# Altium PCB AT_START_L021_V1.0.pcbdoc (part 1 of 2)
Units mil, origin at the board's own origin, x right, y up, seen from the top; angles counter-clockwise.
Board outline 12992.58 x 3605 mil, 2 copper layers (Top Layer, Bottom Layer); 116 components, 109 nets, 471 pads, 502 vias.
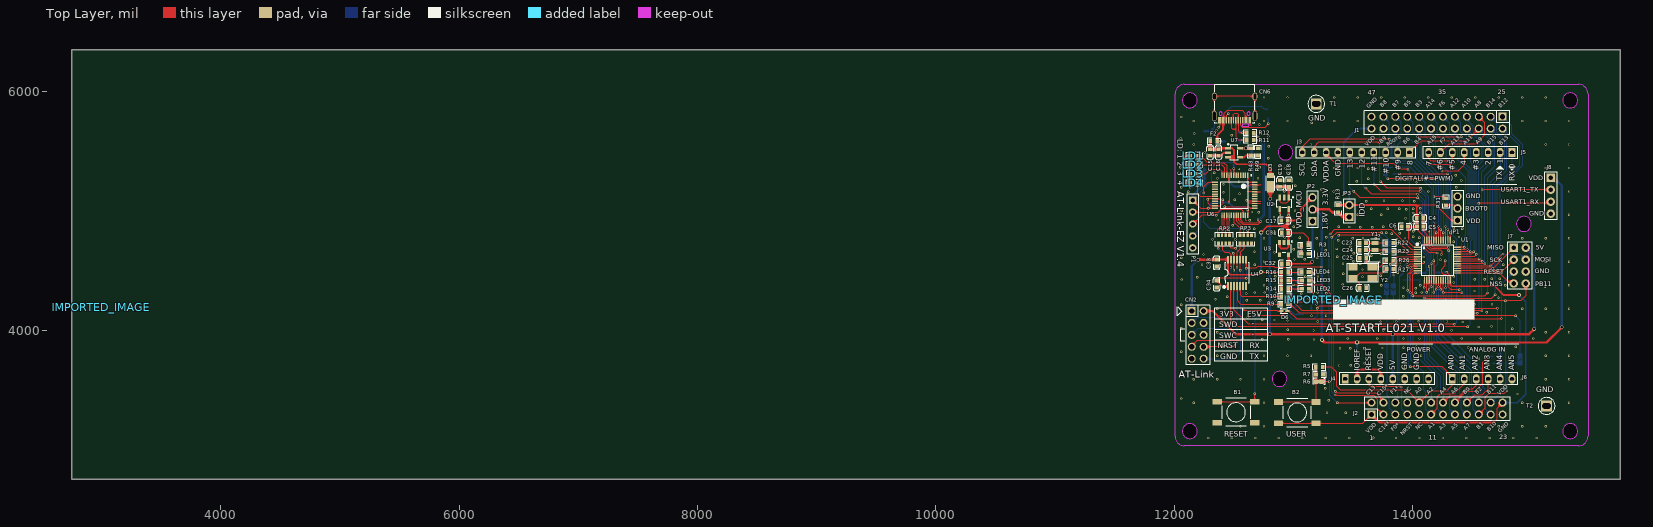
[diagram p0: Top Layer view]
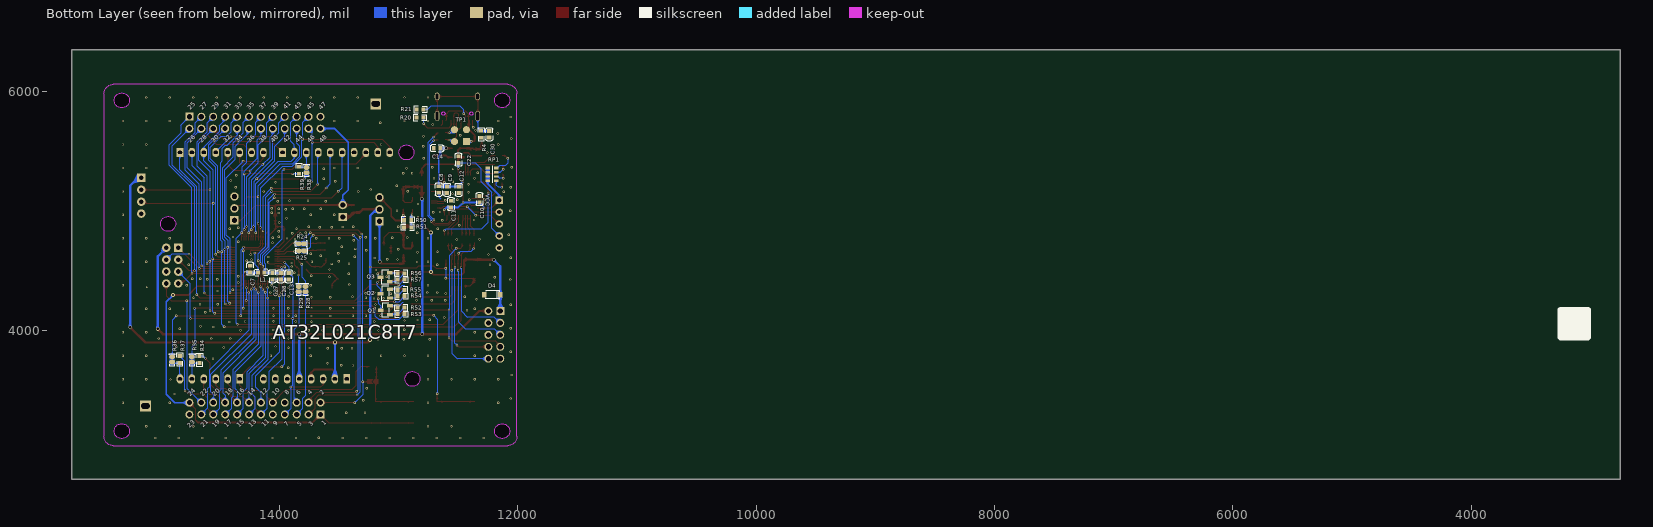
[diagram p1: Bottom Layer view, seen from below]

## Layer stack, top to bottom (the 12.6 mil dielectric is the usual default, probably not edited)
Top Layer: signal copper (thickness not stored)
Dielectric: dielectric 12.6, FR-4, Dk 4.8
Bottom Layer: signal copper (thickness not stored)

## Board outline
15742.58,2750 2750,2750 2750,6355 15742.58,6355
cut-out: 15384.57,5929.2 ccw(c15321.57,5929.2) 15258.58,5929.2 ccw(c15321.57,5929.2)
cut-out: 15384.57,3154.52 ccw(c15321.57,3154.52) 15258.58,3154.52 ccw(c15321.57,3154.52)
cut-out: 12193.58,3154.52 ccw(c12130.59,3154.23) 12067.6,3154.52 ccw(c12130.59,3154.81)
cut-out: 12193.58,5929.2 ccw(c12130.59,5928.92) 12067.6,5929.2 ccw(c12130.59,5929.49)
cut-out: 14996.34,4892.35 ccw(c14933.34,4892.35) 14870.35,4892.35 ccw(c14933.34,4892.35)
cut-out: 12946.34,3592.35 ccw(c12883.34,3592.35) 12820.35,3592.35 ccw(c12883.34,3592.35)
cut-out: 12996.34,5492.35 ccw(c12933.34,5492.35) 12870.35,5492.35 ccw(c12933.34,5492.35)

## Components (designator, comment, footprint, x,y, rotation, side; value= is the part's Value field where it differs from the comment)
B1 "K2-1102SP-C4SC-04" BUTTON_SMT_6*6*5 12517.98,3312.6 r0 top
B2 "K2-1102SP-C4SC-04" BUTTON_SMT_6*6*5 13031.98,3310.61 r180 top
C4 "CL10A475KO8NNNC" C0603 14061.58,4941 r180 top
C5 "CC0603KRX7R9BB104" C0603 14063.58,4871 r180 top
C6 "CC0603KRX7R9BB104" C0603 13933.58,4870 r0 top
C7 "CC0603KRX7R9BB104" C0603 14244.58,4515 r270 bottom
C8 "CL10A475KO8NNNC" C0603 12662.58,5182 r90 bottom
C9 "CC0603KRX7R9BB104" C0603 12592.58,5180 r90 bottom
C10 "CC0603KRX7R9BB104" C0603 12320.58,5100 r270 bottom
C11 "CC0603KRX7R9BB104" C0603 12559.58,5059 r270 bottom
C12 "CC0603KRX7R9BB104" C0603 12495.58,5180 r90 bottom
C13 "CC0603KRX7R9BB104" C0603 13920.58,4453 r90 bottom
C14 "CL10A106KP8NNNC" C0603 12676.58,5527 r180 bottom
C15 "CL10A106KP8NNNC" C0603 12301.58,5492 r90 top
C16 "CC0603KRX7R9BB104" C0603 12371.58,5492 r90 top
C17 "CL10A106KP8NNNC" C0603 12924.58,4921 r0 top
C18 "CL10A106KP8NNNC" C0603 12960.58,5231 r270 top
C19 "CC0603KRX7R9BB104" C0603 12889.58,5232 r270 top
C22 "CC0603KRX7R9BB104" C0603 12496.58,5432 r270 bottom
C23 "CL10C180JB8NNNC" C0603 13581.98,4732.6 r0 top
C24 "CL10C180JB8NNNC" C0603 13581.98,4673.6 r0 top
C25 "CL10C330JB8NNNC" C0603 13582.58,4605 r0 top
C26 "CL10C330JB8NNNC" C0603 13582.58,4355 r180 top
C27 "CL10A105KB8NNNC" C0603 14057.58,4454 r90 bottom
C28 "CC0603KRX7R9BB104" C0603 13988.58,4453 r90 bottom
C30 "CC0603KRX7R9BB104" C0603 12238.9,5644.56 r90 bottom
C31 "CL10A105KB8NNNC" C0603 12928.58,4819 r0 top
C32 "CL10A105KB8NNNC" C0603 12926.58,4558 r0 top
C33 "CC0603KRX7R9BB104" C0603 12355.58,4566 r270 top
C34 "CC0603KRX7R9BB104" C0603 12355.58,4388 r90 top
CN2 "Z-21310110021001" HDR-TH_10P-P2.54-V-M-R2-C5-S2.54 12196.58,3962 r270 top
CN6 "TYPEC-304-BCP16" USB-C-SMD_TYPEC-304-BCP16 12506.58,5862 r180 top
D3 "DFLS130L-7_POWERDI-123_L2.8-W1.8-LS3.7-RD" POWERDI-123_L2.8-W1.8-LS3.7-RD 12805.58,5251 r90 top
D4 "SMF3.3A" SOD-123_L2.8-W1.8-LS3.7-RD 12213.58,4299 r0 bottom
D6 "LRB521S-40T1G" SOD-523_L1.2-W0.8-LS1.6-RD 12924.58,4162 r0 top
F2 "SMD0603B050TF" R0603 12331.58,5587 r180 top
IMPORTED_IMAGE "IMPORTED_IMAGE" IMPORTED_IMAGE 3000,4194 r0 top
IMPORTED_IMAGE "IMPORTED_IMAGE" IMPORTED_IMAGE 13334.58,4257 r0 top
J1 "PZ254V-12-24P" HDR-TH_24P-P2.54-V-M-R2-C12-S2.54 14204.6,5742.09 r180 top
J2 "PZ254V-12-24P" HDR-TH_24P-P2.54-V-M-R2-C12-S2.54 14204.61,3343.91 r0 top
J3 "2.54-1*10P母" "AT-START-Connector 1x10" 13523.35,5492.35 r180 top
J4 "2.54-1*8P母环保" "AT-START-Connector 1x8" 13783.35,3592.35 r0 top
J5 "2.54-1*8P母环保" "AT-START-Connector 1x8" 14483.35,5492.35 r180 top
J6 "2.54-1*6P母" "AT-START-Connector 1x6" 14583.33,3592.35 r0 top
J7 "Header 4X2" HDR2X4 14848.35,4692.9 r270 top
J8 "Header 1x4" HDR1X4 15158.58,5279 r270 top
JP1 "Header 1x3" "HEADER 1X3" 14376.58,4923 r90 top
JP2 "Header 1x3" "HEADER 1X3" 13159.58,4915 r90 top
JP3 "NC(Header 1x2)" HDR1X2 13467.58,4951 r90 top
L1 "600Ω@100MHz ±25%" L0603 14151.58,4485 r180 bottom
LD1 "RED" LED0603 12129.79,5464.85 r0 top
LD2 "GREEN" LED0603 12130.75,5390.75 r0 top
LD3 "BLUE" LED0603 12130.79,5313.85 r0 top
LD4 "YELLOW" LED0603 12130.75,5237.85 r0 top
LED1 "RED_LED0603(1)" LED0603 13066.58,4642 r0 top
LED2 "RED_LED0603" LED0603 13069.58,4349 r0 top
LED3 "YELLOW_LED0603" LED0603 13068.58,4418 r0 top
LED4 "GREEN_LED0603" LED0603 13067.58,4490 r0 top
P1 "HDR-M-2.54_1x5" HDR-M-2.54_1X5 12154.58,4892 r270 top
Q1 "SS8050_C916392" SOT-23-3_L2.9-W1.3-P1.90-LS2.4-BR 13109.58,4169 r180 bottom
Q2 "SS8050_C916392" SOT-23-3_L2.9-W1.3-P1.90-LS2.4-BR 13110.58,4308 r180 bottom
Q3 "SS8050_C916392" SOT-23-3_L2.9-W1.3-P1.90-LS2.4-BR 13112.58,4446 r180 bottom
R3 "0603WAF1001T5E" R0603 13095.58,4715 r0 top
R4 "RC0603FR-071ML" R0603 12306.58,5645 r270 bottom
R5 "0603WAF0000T5E" R0603 13216.58,3693 r0 top
R6 "NC_SB-PAD" SB-PAD#1 13215.58,3570 r0 top
R7 "0603WAF1003T5E" R0603 13217.58,3628 r180 top
R9 "0603WAF3300T5E" R0603 12925.58,4220 r0 top
R10 "0603WAF3300T5E" R0603 12926.58,4285 r0 top
R11 "0603WAF0000T5E" R0603 12636.58,5597 r0 top
R12 "0603WAF0000T5E" R0603 12636.58,5657 r0 top
R13 "0603WAF0000T5E" R0603 13373.58,5021 r90 top
R14 "0603WAF1001T5E" R0603 12926.58,4349 r180 top
R15 "0603WAF1001T5E" R0603 12927.58,4418 r180 top
R16 "0603WAF1001T5E" R0603 12926.58,4489 r180 top
R20 "0603WAF5101T5E" R0603 12820.58,5784 r0 bottom
R21 "0603WAF5101T5E" R0603 12819.58,5853 r0 bottom
R22 "0603WAF0000T5E" R0603 13807.58,4732 r0 top
R23 "0603WAF0000T5E" R0603 13808.58,4660 r0 top
R24 "NC" SB-PAD#1 13814.58,4727 r180 bottom
R25 "NC" SB-PAD#1 13813.58,4666 r180 bottom
R26 "0603WAF0000T5E" R0603 13807.58,4585 r0 top
R27 "0603WAF0000T5E" R0603 13809.58,4515 r0 top
R28 "NC" SB-PAD#2 13780.58,4345 r270 bottom
R29 "NC" SB-PAD#2 13837.58,4345 r270 bottom
R31 "0603WAF1002T5E" R0603 14279.58,5079 r90 top
R34 "0603WAF0000T5E" R0603 14670.58,3755 r270 bottom
R35 "NC_SB-PAD" SB-PAD#2 14733.58,3755 r270 bottom
R36 "NC_SB-PAD" SB-PAD#2 14899.58,3755 r270 bottom
R37 "0603WAF0000T5E" R0603 14835.58,3756 r270 bottom
R38 "NC_SB-PAD" SB-PAD#2 13772.58,5343 r270 bottom
R39 "0603WAF0000T5E" R0603 13834.58,5343 r90 bottom
R43 "0603WAF4702T5E" R0603 12641.58,5497 r90 top
R49 "0603WAF1502T5E" R0603 12701.58,5497 r270 top
R50 "0603WAF4702T5E" R0603 12923.58,4927 r0 bottom
R51 "0603WAF1502T5E" R0603 12923.58,4864 r180 bottom
R52 "0603WAF1003T5E" R0603 12978.58,4190 r180 bottom
R53 "0603WAF1002T5E" R0603 12979.13,4136 r0 bottom
R54 "0603WAF1002T5E" R0603 12978.58,4286 r0 bottom
R55 "0603WAF1003T5E" R0603 12978.58,4339 r180 bottom
R56 "0603WAF1003T5E" R0603 12978.58,4478 r180 bottom
R57 "0603WAF1002T5E" R0603 12978.58,4425 r0 bottom
RP1 "1K" 0603*4,8P4R 12251.58,5362 r270 bottom
RP2 "4D03WGJ0331T5E" RES-ARRAY-SMD_0603-8P-L3.2-W1.6-BL 12416.58,4763 r0 top
RP3 "4D03WGJ0331T5E" RES-ARRAY-SMD_0603-8P-L3.2-W1.6-BL 12599.58,4763 r0 top
T1 "Testpoint_TESTHOOK" TESTHOOK 13191.58,5900 r0 top
T2 "Testpoint" TESTHOOK 15123.58,3366 r180 top
TP1 "1X4P_2.54F" "HDR1X4 - TOP" 12530.58,5483 r270 bottom
U1 "AT32L021C8T7" LQFP-48_L7.0-W7.0-P0.50-LS9.0-BL 14206.98,4588.6 r270 top
U2 "RT9080N-08GJ5" SOT-23-5 12860.58,5051 r270 top
U3 "ME6211C18M5G-N" SOT-23-5_L3.0-W1.7-P0.95-LS2.8-BR 12921.58,4685 r90 top
U4 "RS0104YQ" TSSOP-14_L5.0-W4.4-P0.65-LS6.4-BL 12526.58,4482 r0 top
U6 "AT32F403ACCT7" "LQFP48 - 2" 12616.98,5300.6 r270 top
U7 "RT9080N-08GJ5" SOT-23-5(1) 12516.58,5427 r0 top
Y1 "32.768KHz" "XTAL_SOP - FC-12M" 13685.98,4732.6 r270 top
Y2 "8MHz" OSC-SMD_4P-L5.0-W3.2-BL 13580.58,4482 r180 top

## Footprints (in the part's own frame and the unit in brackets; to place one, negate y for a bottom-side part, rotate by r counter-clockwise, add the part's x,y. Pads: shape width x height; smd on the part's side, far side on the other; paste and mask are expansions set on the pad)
0603*4,8P4R [mm]
  rect 0.55x0.95 smd: 1(0,0) 4(2.7,0) 5(2.7,1.85) 8(0,1.85)
  rect 0.5x0.95 smd: 2(0.9,0) 3(1.8,0) 6(1.8,1.85) 7(0.9,1.85)
  silkscreen extent -0.43,0.94 3.1,0.94
"AT-START-Connector 1x6" [mm]
  rect 1.4x2 hole 0.65 slot 0.9 at 0 deg: 1(-6.35,0)
  oval 1.4x2 hole 0.65 slot 0.9 at 0 deg: 2(-3.81,0) 3(-1.27,0) 4(1.27,0) 5(3.81,0) 6(6.35,0)
  silkscreen extent -7.62,-1.17 7.62,1.27
"AT-START-Connector 1x8" [mm]
  rect 1.4x2 hole 0.65 slot 0.9 at 0 deg: 1(-8.89,0)
  oval 1.4x2 hole 0.65 slot 0.9 at 0 deg: 2(-6.35,0) 3(-3.81,0) 4(-1.27,0) 5(1.27,0) 6(3.81,0) 7(6.35,0) 8(8.89,0)
  silkscreen extent -10.16,-1.17 10.16,1.27
"AT-START-Connector 1x10" [mm]
  rect 1.4x2 hole 0.65 slot 0.9 at 0 deg: 1(-11.43,0)
  oval 1.4x2 hole 0.65 slot 0.9 at 0 deg: 2(-8.89,0) 3(-6.35,0) 4(-3.81,0) 5(-1.27,0) 6(1.27,0) 7(3.81,0) 8(6.35,0) 9(8.89,0) 10(11.43,0)
  silkscreen extent -12.7,-1.17 12.67,1.27
BUTTON_SMT_6*6*5 [mm]
  rect 2x1.2 smd: 1(-4,2.25) 2(4,2.25) 3(-4,-2.25) 4(4,-2.25)
  silkscreen extent -3,-3 3,3
C0603 [mm]
  rect 0.8x0.9 smd: 1(-0.7,0) 2(0.7,0)
  silkscreen extent -1.41,-0.71 1.39,0.72
HDR1X2 [mm]
  rect 1.8x1.8 hole 1 slot 1.005 at 0 deg: 1(0,0)
  round 1.8 hole 1 slot 1.005 at 0 deg: 2(2.54,0)
  silkscreen extent -1.27,-1.27 3.81,1.27
HDR1X4 [mm]
  rect 1.8x1.8 hole 1: 1(0,0)
  round 1.8 hole 1: 2(2.54,0) 3(5.08,0) 4(7.62,0)
  silkscreen extent -1.27,-1.27 8.89,1.27
"HDR1X4 - TOP" [mm]
  rect 1.5x1.5 smd: 1(-2.54,2.54)
  round 1.5 smd: 2(-5.08,0) 3(-2.54,0) 4(-5.08,2.54)
HDR2X4 [mm]
  rect 1.8x1.8 hole 1: 1(0,0)
  round 1.8 hole 1: 2(0,2.54) 3(2.54,0) 4(2.54,2.54) 5(5.08,0) 6(5.08,2.54) 7(7.62,0) 8(7.62,2.54)
  silkscreen extent -1.27,-1.27 8.89,3.81
HDR-M-2.54_1X5 [mil]
  rect 62x62 hole 35: 1(-200,0)
  round 62 hole 35: 2(-100,0) 3(0,0) 4(100,0) 5(200,0)
  silkscreen extent -250,-50 250,50
HDR-TH_10P-P2.54-V-M-R2-C5-S2.54 [mm]
  rect 1.7x1.7 hole 1.1: 1(-5.08,-1.27)
  round 1.7 hole 1.1: 2(-5.08,1.27) 3(-2.54,-1.27) 4(-2.54,1.27) 5(0,-1.27) 6(0,1.27) 7(2.54,-1.27) 8(2.54,1.27) 9(5.08,-1.27) 10(5.08,1.27)
  silkscreen extent -6.35,-2.54 6.35,2.54
HDR-TH_24P-P2.54-V-M-R2-C12-S2.54 [mil]
  rect 66.9x66.9 hole 43.3: 1(-550,-50)
  round 66.9 hole 43.3: 2(-550,50) 3(-450,-50) 4(-450,50) 5(-350,-50) 6(-350,50) 7(-250,-50) 8(-250,50) 9(-150,-50) 10(-150,50) 11(-50,-50) 12(-50,50) 13(50,-50) 14(50,50) 15(150,-50) 16(150,50) 17(250,-50) 18(250,50) 19(350,-50) 20(350,50) 21(450,-50) 22(450,50) 23(550,-50) 24(550,50)
  silkscreen extent -609,-100 609,100
"HEADER 1X3" [mm]
  rect 1.8x1.8 hole 1 slot 1.005 at 0 deg: 1(0,0)
  round 1.8 hole 1 slot 1.005 at 0 deg: 2(2.54,0) 3(5.08,0)
  silkscreen extent -1.27,-1.27 6.35,1.27
IMPORTED_IMAGE [mil]
L0603 [mil]
  rect 31.5x34 smd: 1(-27.6,0) 2(27.6,0)
  silkscreen extent -56,-26 56,26
LED0603 [mil]
  rect 36x32 smd: 1(-0.04,0.2) 2(60.96,0.2)
  silkscreen extent -28,-28 110,27
"LQFP48 - 2" [mm]
  rect 1.2x0.3 smd: 1(0,0) 2(0,-0.5) 3(0,-1) 4(0,-1.5) 5(0,-2) 6(0,-2.5) 7(0,-3) 8(0,-3.5) 9(0,-4) 10(0,-4.5) 11(0,-5) 12(0,-5.5) 25(8.5,-5.5) 26(8.5,-5) 27(8.5,-4.5) 28(8.5,-4) 29(8.5,-3.5) 30(8.5,-3) 31(8.5,-2.5) 32(8.5,-2) 33(8.5,-1.5) 34(8.5,-1) 35(8.5,-0.5) 36(8.5,0)
  rect 0.3x1.2 smd: 13(1.5,-7) 14(2,-7) 15(2.5,-7) 16(3,-7) 17(3.5,-7) 18(4,-7) 19(4.5,-7) 20(5,-7) 21(5.5,-7) 22(6,-7) 23(6.5,-7) 24(7,-7) 37(7,1.5) 38(6.5,1.5) 39(6,1.5) 40(5.5,1.5) 41(5,1.5) 42(4.5,1.5) 43(4,1.5) 44(3.5,1.5) 45(3,1.5) 46(2.5,1.5) 47(2,1.5) 48(1.5,1.5)
  silkscreen extent -0.12,-5.71 7.11,0.89
LQFP-48_L7.0-W7.0-P0.50-LS9.0-BL [mil]
  oval 10.6x59.1 smd: 1(-108.3,-167.3) 2(-88.6,-167.3) 3(-68.9,-167.3) 4(-49.2,-167.3) 5(-29.5,-167.3) 6(-9.8,-167.3) 7(9.8,-167.3) 8(29.5,-167.3) 9(49.2,-167.3) 10(68.9,-167.3) 11(88.6,-167.3) 12(108.3,-167.3) 25(108.3,167.3) 26(88.6,167.3) 27(68.9,167.3) 28(49.2,167.3) 29(29.5,167.3) 30(9.8,167.3) 31(-9.8,167.3) 32(-29.5,167.3) 33(-49.2,167.3) 34(-68.9,167.3) 35(-88.6,167.3) 36(-108.3,167.3)
  oval 59.1x10.6 smd: 13(167.3,-108.3) 14(167.3,-88.6) 15(167.3,-68.9) 16(167.3,-49.2) 17(167.3,-29.5) 18(167.3,-9.8) 19(167.3,9.8) 20(167.3,29.5) 21(167.3,49.2) 22(167.3,68.9) 23(167.3,88.6) 24(167.3,108.3) 37(-167.3,108.3) 38(-167.3,88.6) 39(-167.3,68.9) 40(-167.3,49.2) 41(-167.3,29.5) 42(-167.3,9.8) 43(-167.3,-9.8) 44(-167.3,-29.5) 45(-167.3,-49.2) 46(-167.3,-68.9) 47(-167.3,-88.6) 48(-167.3,-108.3)
  silkscreen extent -141,-176 130,132
OSC-SMD_4P-L5.0-W3.2-BL [mm]
  rect 2x1.4 smd: 1(-2.05,-1.2) 2(2.05,-1.2) 3(2.05,1.2) 4(-2.05,1.2)
  silkscreen extent -3.46,-2.26 3.24,2.03
POWERDI-123_L2.8-W1.8-LS3.7-RD [mm]
  rect 2.4x1.5 smd: 1(-1.187,0)
  rect 1.05x1.5 smd: 2(1.187,0)
  silkscreen extent -2,-1 1.2,1
R0603 [mil]
  rect 31.75x34.02 smd: 1(-29.66,0) 2(29.66,0)
  silkscreen extent -55,-26 55,26
RES-ARRAY-SMD_0603-8P-L3.2-W1.6-BL [mm]
  rect 0.65x0.8 smd: 1(-1.2,-0.9) 4(1.2,-0.9) 5(1.2,0.9) 8(-1.2,0.9)
  rect 0.5x0.8 smd: 2(-0.4,-0.9) 3(0.4,-0.9) 6(0.4,0.9) 7(-0.4,0.9)
  silkscreen extent -1.87,-1.45 1.87,1.47
SB-PAD#1 [mm]
  oval 1.225x1 smd: 1(-0.587,0)
  oval 1.319x1 smd: 2(0.541,0)
  Top Layer region: -1.2,-0.5 -1.2,0.5 -0.418,0.5 0.025,0 -0.433,-0.5
  Top Layer region: -0.119,0.5 0.381,0 -0.119,-0.5 1.2,-0.5 1.2,0.5
  silkscreen extent -1.28,-0.58 1.28,0.58
SB-PAD#2 [mm]
  oval 1x1.225 smd: 1(-0.587,0)
  oval 1x1.319 smd: 2(0.541,0)
  Top Layer region: -1.2,-0.5 -1.2,0.5 -0.418,0.5 0.025,0 -0.433,-0.5
  Top Layer region: -0.119,0.5 0.381,0 -0.119,-0.5 1.2,-0.5 1.2,0.5
  silkscreen extent -1.28,-0.58 1.28,0.58
SOD-123_L2.8-W1.8-LS3.7-RD [mm]
  rect 0.95x1.15 smd: 1(-1.692,0) 2(1.692,0)
  silkscreen extent -1.63,-0.94 1.41,0.94
SOD-523_L1.2-W0.8-LS1.6-RD [mm]
  rect 0.93x0.36 smd: 1(-0.635,0) 2(0.635,0)
  silkscreen extent -0.91,-0.55 0.68,0.55
SOT-23-3_L2.9-W1.3-P1.90-LS2.4-BR [mm]
  rect 1.25x0.7 smd: 1(1,-0.95) 2(1,0.95) 3(-1,0)
  silkscreen extent -0.73,-1.53 0.73,1.53
SOT-23-5 [mil]
  rect 50x20 smd: 1(-65,100) 2(-65,63) 3(-65,25) 4(35,25) 5(35,100)
  silkscreen extent -65,1 18,135
SOT-23-5(1) [mil]
  rect 50x20 smd: 1(-65,100) 2(-65,63) 3(-65,25) 4(35,25) 5(35,100)
  silkscreen extent -65,1 18,135
SOT-23-5_L3.0-W1.7-P0.95-LS2.8-BR [mm]
  rect 1x0.6 smd: 1(1.3,-0.95) 2(1.3,0) 3(1.3,0.95) 4(-1.3,0.95) 5(-1.3,-0.95)
  silkscreen extent -0.9,-1.78 1.65,1.55
TESTHOOK [mm]
  rect 2.3x2.3 hole 1.2 slot 1.8 at 0 deg: 1(0,0)
  silkscreen extent -1.79,-1.8 1.8,1.8
TSSOP-14_L5.0-W4.4-P0.65-LS6.4-BL [mm]
  rect 0.4x1.7 smd: 1(-1.95,-2.8) 2(-1.3,-2.8) 3(-0.65,-2.8) 4(0,-2.8) 5(0.65,-2.8) 6(1.3,-2.8) 7(1.95,-2.8) 8(1.95,2.8) 9(1.3,2.8) 10(0.65,2.8) 11(0,2.8) 12(-0.65,2.8) 13(-1.3,2.8) 14(-1.95,2.8)
  silkscreen extent -2.95,-3.2 2.5,2.25
USB-C-SMD_TYPEC-304-BCP16 [mil]
  oval 39.4x82.7 hole 23.6 slot 70.9 at 90 deg: 13(-170.1,64.3) 14(170.1,64.3)
  oval 39.4x63 hole 23.6 slot 47.2 at 90 deg: 15(-170.1,-100.3) 16(170.1,-100.3)
  rect 23.6x57.1 smd: A1B12(-127,100.3) A4B9(-96.5,100.3) B1A12(126.8,100.3) B4A9(96.5,100.3)
  rect 11.8x57.1 smd: A5(-49.2,100.3) A6(-9.8,100.3) A7(9.8,100.3) A8(49.2,100.3) B5(68.9,100.3) B6(29.5,100.3) B7(-29.5,100.3) B8(-68.9,100.3)
  Multi-Layer board cut-out: 103.5,43.4 104.87,37.41 108.7,32.61 114.23,29.94 120.37,29.94 125.91,32.61 129.74,37.41 131.11,43.4 131.11,43.4 129.74,49.39 125.91,54.19 120.37,56.86 114.23,56.86 108.7,54.19 104.87,49.39 103.5,43.4
  Multi-Layer board cut-out: -131.1,43.4 -129.73,37.41 -125.9,32.61 -120.37,29.94 -114.23,29.94 -108.69,32.61 -104.86,37.41 -103.49,43.4 -103.49,43.4 -104.86,49.39 -108.69,54.19 -114.23,56.86 -120.37,56.86 -125.9,54.19 -129.73,49.39 -131.1,43.4
  Multi-Layer keep-out region: 103.5,43.4 104.87,37.41 108.7,32.61 114.23,29.94 120.37,29.94 125.91,32.61 129.74,37.41 131.11,43.4 131.11,43.4 129.74,49.39 125.91,54.19 120.37,56.86 114.23,56.86 108.7,54.19 104.87,49.39 103.5,43.4
  Multi-Layer keep-out region: -131.1,43.4 -129.73,37.41 -125.9,32.61 -120.37,29.94 -114.23,29.94 -108.69,32.61 -104.86,37.41 -103.49,43.4 -103.49,43.4 -104.86,49.39 -108.69,54.19 -114.23,56.86 -120.37,56.86 -125.9,54.19 -129.73,49.39 -131.1,43.4
  silkscreen extent -170,-200 170,120
"XTAL_SOP - FC-12M" [mm]
  rect 0.8x1.5 smd: 1(0,0) 2(1.5,0)
  silkscreen extent -0.81,-0.99 2.29,0.94

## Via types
v1: diameter 19.68, hole 11.81, Top Layer to Bottom Layer, 217 vias
v2: diameter 19.7, hole 11.8, Top Layer to Bottom Layer, 181 vias
v3: diameter 19.7, hole 11.81, Top Layer to Bottom Layer, 91 vias
v4: diameter 31.5, hole 19.68, Top Layer to Bottom Layer, 13 vias

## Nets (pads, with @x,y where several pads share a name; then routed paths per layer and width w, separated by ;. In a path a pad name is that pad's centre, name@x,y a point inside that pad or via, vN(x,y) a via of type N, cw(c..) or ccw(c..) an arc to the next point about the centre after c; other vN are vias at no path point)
1V8: C32.2 JP2.1 U3.5 | length 629.7
  Top Layer w15: U3.5@12958.98,4633.81 12958.98,4562.84 C32.2@12954.14,4558 13141.58,4558 v4(13158.58,4575)
  Bottom Layer w15: v4(13158.58,4575) 13159.58,4576.01 JP2.1@13159.59,4915
3V3: C17.2 C31.2 C33.1 CN2.1 D4.1 JP2.3 R3.2 R14.2 R15.2 R16.2 R50.2 U2.5 U3.1 U3.3 U4.14 | length 3048.3
  Top Layer w10: v4(12727.58,4489) R16.2@12896.92,4489 R14.2@12896.92,4349 ; C31.2@12956.14,4819 13083.58,4819 13125.24,4777.34 R3.2@13125.24,4715
  Top Layer w15: C33.1@12355.58,4593.56 12448.49,4593.56 U4.14@12449.81,4592.24 12449.81,4487.77 12470.58,4467 12706.58,4467 12727.58,4488 v4(12727.58,4489) ; v4(12728.58,4821) 12780.44,4872.87 12952.14,4872.87 ; U3.3@12884.17,4736.19 12884.17,4700.4 12898.58,4686 12944.58,4686 12958.98,4700.4 U3.1@12958.98,4736.19 12958.98,4816.16 C31.2@12956.14,4819 12952.14,4823 12952.14,4872.87 ; U2.5@12960.58,5016 v3(12960.58,4966.73) 12952.14,4958.29 C17.2@12952.14,4921 ; JP2.3@13159.59,5115 13061.58,5016.99 13061.58,4958 13024.58,4921 C17.2@12952.14,4921 ; 12952.14,4872.87 C17.2@12952.14,4921
  Top Layer w20: v4(12201.58,4592) 12203.14,4593.56 C33.1@12355.58,4593.56
  Bottom Layer w6: R50.2@12953.24,4927 12960.58,4934.34 v3(12960.58,4966.73)
  Bottom Layer w15: v4(12727.58,4489) 12727.58,4820 v4(12728.58,4821)
  Bottom Layer w20: CN2.1@12146.58,4162 D4.1@12146.58,4298.63 ; D4.1@12146.94,4299 D4.1@12146.58,4298.63 ; v4(12201.58,4592) 12146.58,4537 D4.1@12146.58,4298.63
$1N349: LD4.1 RP1.5 | length 131.5
  Top Layer w6: LD4.1@12130.7,5238.05 12130.7,5200.87 v1(12132.58,5199)
  Bottom Layer w6: v1(12132.58,5199) 12159.58,5199 12178.75,5218.17 RP1.5@12178.75,5255.7
$1N350: LD3.1 RP1.6 | length 103.9
  Top Layer w6: v1(12121.58,5277) 12121.58,5304.88 LD3.1@12130.75,5314.05
  Bottom Layer w6: v1(12121.58,5277) 12152.54,5277 12166.67,5291.13 RP1.6@12178.75,5291.13
$1N351: LD2.1 RP1.7 | length 110.4
  Top Layer w6: v1(12121.58,5352) 12121.58,5381.82 LD2.1@12130.7,5390.95
  Bottom Layer w6: v1(12121.58,5352) 12147,5326.57 RP1.7@12178.75,5326.57
$1N352: LD1.1 RP1.8 | length 211.2
  Top Layer w6: v1(12082.58,5444) 12103.62,5465.05 LD1.1@12129.75,5465.05
  Bottom Layer w6: v1(12082.58,5444) 12082.58,5401 12100.58,5383 12150.58,5383 12171.58,5362 RP1.8@12178.75,5362
$1N495: R43.1 R49.2 U7.4 | length 156.4
  Top Layer w15: U7.4@12551.58,5452 12586.57,5452 12601.92,5467.34 R43.1@12641.58,5467.34 R49.2@12701.58,5467.34
$1N28282: C15.2 C16.2 D3.2 F2.2 U7.1 U7.3 | length 810.1
  Top Layer w15: C15.2@12301.58,5519.56 C15.2@12301.92,5519.9 ; F2.2@12301.92,5587 C15.2@12301.92,5519.9 ; C16.2@12371.58,5519.56 C16.2@12371.24,5519.9 ; U7.3@12451.58,5452 12500.58,5452 ; D3.2@12805.58,5297.75 12805.58,5358 12770.58,5393 12523.58,5393 12500.58,5416 12500.58,5452 ; C15.2@12301.92,5519.9 C16.2@12371.24,5519.9 ; C16.2@12371.24,5519.9 12378.33,5527 U7.1@12451.58,5527 12485.58,5527 12500.58,5512 12500.58,5452
$2N102: C25.2 R26.1 Y2.1 | length 243.7
  Top Layer w6: C25.2@13610.14,4605 13610.14,4568.44 13649.33,4529.24 Y2.1@13661.28,4529.24 13666.05,4534 13726.92,4534 R26.1@13777.92,4585
$2N103: C26.2 R27.1 Y2.3 | length 412
  Top Layer w6: Y2.3@13499.86,4434.76 Y2.3@13511.33,4434.76 ; C26.2@13555.01,4355 13555.01,4392.56 13512.82,4434.76 Y2.3@13511.33,4434.76 ; R27.1@13779.92,4515 13744.92,4480 13556.58,4480 Y2.3@13511.33,4434.76
$2N208: C24.2 R23.1 Y1.2 | length 174.9
  Top Layer w6: C24.2@13609.53,4673.6 Y1.2@13685.92,4673.6 ; Y1.2@13685.98,4673.54 13765.38,4673.54 R23.1@13778.92,4660
$2N210: C23.2 R22.1 Y1.1 | length 168.6
  Top Layer w6: C23.2@13609.53,4732.6 Y1.1@13685.98,4732.6 13777.32,4732.6 R22.1@13777.92,4732
$2N318: JP1.2 R31.1 | length 107.9
  Top Layer w6: R31.1@14279.58,5049.34 14350.25,5049.34 JP1.2@14376.59,5023
$3N170: LED3.1 R15.1 | length 111.4
  Top Layer w10: R15.1@12957.24,4418 13068.33,4418 LED3.1@13068.53,4418.2
$3N172: LED4.1 R16.1 | length 111.8
  Top Layer w10: R16.1@12956.24,4489 13066.33,4489 LED4.1@13067.53,4490.2
$3N175: LED3.2 Q2.3 | length 160
  Top Layer w6: LED3.2@13129.53,4418.2 13162.37,4418.2 v1(13176.58,4404)
  Bottom Layer w6: Q2.3@13149.94,4308 13149.94,4345.37 13176.58,4372 v1(13176.58,4404)
$3N177: LED4.2 Q3.3 | length 101.4
  Top Layer w6: LED4.2@13128.53,4490.2 13159.37,4490.2 v1(13173.58,4476)
  Bottom Layer w6: Q3.3@13151.94,4446 13171.58,4446 13173.58,4448 v1(13173.58,4476)
$3N21573: B2.3 B2.4 R5.1 R6.1 R7.2 | length 612.3
  Top Layer w6: B2.4@12874.5,3399.2 B2.3@13189.45,3399.2 13189.45,3567 R6.1@13192.45,3570 13187.92,3574.54 R7.2@13187.92,3628 13186.92,3629 R5.1@13186.92,3693
$3N23578: R10.1 U4.5 | length 423.9
  Top Layer w6: U4.5@12552.17,4371.76 12552.17,4299.41 12568.58,4283 R10.1@12896.92,4283
$3N26346: R50.1 R51.2 U2.4 | length 155.5
  Top Layer w10: U2.4@12885.58,5016 12886.58,5015 v1(12886.58,4969)
  Bottom Layer w10: v1(12886.58,4969) 12893.92,4961.66 R50.1@12893.92,4927 R51.2@12893.92,4864
$3N27254: LED1.1 R3.1 | length 73.1
  Top Layer w10: R3.1@13065.92,4715 13065.92,4642.82 LED1.1@13066.53,4642.2
$3N29129: R9.1 U4.4 | length 502.4
  Top Layer w6: U4.4@12526.58,4371.76 12526.58,4252 12558.58,4220 R9.1@12895.92,4220
$3N31026: LED2.1 R14.1 | length 113.4
  Top Layer w10: R14.1@12956.24,4349 13069.33,4349 LED2.1@13069.53,4349.2
$3N31027: LED2.2 Q1.3 | length 206.6
  Top Layer w6: LED2.2@13130.53,4349.2 13171.58,4308.16 v1(13171.58,4265)
  Bottom Layer w6: Q1.3@13148.94,4169 13148.94,4205.37 13171.58,4228 v1(13171.58,4265)
$3N31068: Q1.1 R52.2 R53.2 | length 173.6
  Bottom Layer w6: R52.2@12948.92,4190 12950.79,4190 R52.2@12952.79,4192 ; R52.2@12949.47,4195.32 R52.2@12952.79,4192 ; R52.2@12958.79,4198 R52.2@12952.79,4192 ; Q1.1@13082.2,4131.6 13077.81,4136 R53.2@13008.79,4136 13006.58,4136 12952.79,4189.79 R52.2@12952.79,4192
$3N31207: Q2.1 R54.2 R55.2 | length 161.6
  Bottom Layer w6: R55.2@12948.92,4339 12955.24,4339 R54.2@13008.24,4286 13023.64,4270.6 Q2.1@13082.2,4270.6
$3N31389: Q3.1 R56.2 R57.2 | length 154.7
  Bottom Layer w6: R56.2@12957.92,4478 12957.92,4469.51 13001.92,4425.51 R57.2@13001.92,4425 ; R57.2@13008.24,4427.68 R57.2@13008.24,4425 13024.64,4408.6 Q3.1@13082.2,4408.6
$4N197: J6.5 R34.2 R35.2 | length 206.2
  Bottom Layer w6: R34.2@14670.58,3725.34 14672.92,3723 R35.2@14730.85,3723 ; J6.5@14733.33,3592.35 14733.33,3723 R35.2@14730.85,3723 ; R35.2@14733.58,3733.72 14730.85,3731 R35.2@14730.85,3723
$4N198: J6.6 R36.2 R37.2 | length 203.1
  Bottom Layer w6: J6.6@14833.33,3592.35 14835.58,3594.6 R37.2@14835.58,3726.34 14836.92,3725 14890.85,3725 R36.2@14899.58,3733.72
$4N262: J3.3 R38.1 R39.2 | length 190.2
  Bottom Layer w6: J3.3@13773.35,5492.35 13773.35,5366.89 13828.81,5366.89 R39.2@13834.58,5372.66
  Bottom Layer w10: R38.1@13772.58,5366.12 R38.1@13773.35,5366.89
ATLINK_5V: CN6.A4B9 CN6.B4A9 F2.1 TP1.1 | length 585.6
  Top Layer w10: CN6.B4A9@12410.08,5761.7 12415.58,5767.2 12415.58,5818 12439.58,5842 12574.58,5842 12597.58,5819 12597.58,5767.2 CN6.A4B9@12603.08,5761.7
  Top Layer w15: v1(12390.58,5585) 12388.58,5587 F2.1@12361.24,5587 12361.24,5637.64 12410.08,5686.48 CN6.B4A9@12410.08,5761.7
  Bottom Layer w15: v1(12390.58,5585) 12428.58,5585 TP1.1@12430.58,5583
ATLK_NRST: CN2.7 D6.1 RP2.4 | length 1651
  Top Layer w6: CN2.7@12146.58,3862 12146.58,3872 12187.58,3913 12552.58,3913 v3(12576.58,3937) ; RP2.4@12463.82,4727.56 12463.82,4703.76 12478.58,4689 12513.58,4689 v1(12514.58,4688) ; v1(12576.58,4170) 12861.58,4170 12869.58,4162 D6.1@12899.58,4162
  Bottom Layer w6: v1(12514.58,4688) 12575.58,4627 12575.58,4171 v1(12576.58,4170) v3(12576.58,3937)
ATLK_RX: CN2.10 RP3.2 U4.10 | length 1258.5
  Top Layer w6: v1(12552.58,4504) 12552.17,4504.41 U4.10@12552.17,4592.24 12552.17,4653.59 12583.58,4685 12583.58,4727.31 RP3.2@12583.83,4727.56
  Bottom Layer w6: CN2.10@12246.58,3762 12507.58,3762 12552.58,3807 v1(12552.58,4504)
ATLK_SWCLK: CN2.5 RP2.1 U4.12 | length 1169.5
  Top Layer w6: RP2.1@12366.58,4733.34 12366.58,4688 v1(12368.58,4686) ; v1(12495.58,4648) 12500.99,4642.59 U4.12@12500.99,4592.24 12500.99,4505.41 v1(12500.58,4505)
  Bottom Layer w6: CN2.5@12146.58,3962 12196.58,4012 12441.58,4012 12500.58,4071 v1(12500.58,4505) ; v1(12368.58,4686) 12389.58,4665 12478.58,4665 v1(12495.58,4648)
ATLK_SWDIO: CN2.3 RP2.2 U4.13 | length 986.9
  Top Layer w6: RP2.2@12400.83,4727.56 12400.83,4675.75 12421.58,4655 12458.58,4655 12475.4,4638.18 U4.13@12475.4,4592.24 12475.4,4527.18 v1(12475.58,4527)
  Bottom Layer w6: CN2.3@12146.58,4062 12195.58,4111 12421.58,4111 12475.58,4165 v1(12475.58,4527)
ATLK_TX: CN2.8 RP3.1 U4.11 | length 1138.1
  Top Layer w6: CN2.8@12246.58,3862 12495.58,3862 v2(12509.58,3876) ; v3(12526.58,4530) U4.11@12526.58,4592.24 12526.58,4659 12552.33,4684.76 RP3.1@12552.33,4727.56
  Bottom Layer w6: v2(12509.58,3876) 12526.58,3893 v3(12526.58,4530)
BOOT0: J1.20 R31.2 U1.44 | length 1259
  Top Layer w6: U1.44@14177.48,4755.9 14177.48,4894.9 v1(14178.58,4896) ; v1(14178.58,5120) 14268.24,5120 R31.2@14279.58,5108.66
  Bottom Layer w6: J1.20@13854.6,5692.09 13854.6,5571.02 13828.58,5545 13828.58,5460 13889.58,5399 13991.58,5399 14177.58,5213 v1@14177.58,5119.7 ; v1(14178.58,4896) 14178.58,5118.7 v1@14177.58,5119.7 ; v1(14178.58,5120) 14177.87,5120 v1@14177.58,5119.7
CC1: CN6.A5 R20.1 | length 349.7
  Top Layer w6: CN6.A5@12555.77,5761.7 12555.77,5719.8 12575.58,5700 12757.58,5700 v3(12789.58,5732)
  Bottom Layer w6: v3(12789.58,5732) 12789.58,5782.66 R20.1@12790.92,5784
CC2: CN6.B5 R21.1 | length 455.2
  Top Layer w6: CN6.B5@12437.67,5761.7 12437.67,5802.1 v1(12453.58,5818)
  Bottom Layer w6: v1(12453.58,5818) 12453.58,5852 12480.58,5879 12729.58,5879 12755.58,5853 R21.1@12789.92,5853
E5V: C18.2 C19.2 CN2.2 D3.1 J4.5 J7.2 U2.1 U2.3 | length 5591.7
  Top Layer w10: U2.3@12885.58,5116 12885.58,5082 12898.58,5069 12943.58,5069 12960.58,5086 U2.1@12960.58,5116
  Top Layer w15: D3.1@12805.58,5204.25 12959.76,5204.25 C18.2@12960.58,5203.44 U2.1@12960.58,5116
  Top Layer w20: CN2.2@12246.58,4162 12322.58,4162 12516.58,3968 v4(12800.58,3968) v4(13833.58,3968) 14976.58,3968 v4(15020.58,4012) ; v4(12805.58,5104) D3.1@12805.58,5204.25
  Bottom Layer w20: v4(12800.58,3968) 12800.58,5099 v4(12805.58,5104) ; J4.5@13833.35,3592.35 13833.35,3967.77 v4(13833.58,3968) ; J7.2@14948.35,4692.9 15020.58,4620.68 v4(15020.58,4012)
EGND: C30.2 CN6.13 CN6.14 CN6.15 CN6.16 R4.1 | length 873.6
  Top Layer w10: CN6.14@12336.48,5797.7 CN6.16@12336.48,5962.3 CN6.15@12676.67,5962.3 CN6.13@12676.67,5797.7
  Bottom Layer w10: C30.2@12238.9,5672.12 12304.03,5672.12 R4.1@12306.58,5674.66 12336.48,5704.56 CN6.14@12336.48,5797.7
GND: B1.3 B1.4 C4.1 C5.1 C6.1 C7.1 C8.1 C9.1 C10.1 C11.1 C12.1 C13.1 C14.1 C15.1 C16.1 C17.1 C18.1 C19.1 C22.1 C23.1 C24.1 C25.1 C26.1 C27.1 C28.1 C30.1 C31.1 C32.1 C33.2 C34.1 CN2.9 CN6.A1B12 CN6.B1A12 D4.2 J1.23 J2.23 J3.7 J4.6 J4.7 J7.6 J8.4 JP1.3 LED1.2 P1.5 Q1.2 Q2.2 Q3.2 R4.2 R7.1 R20.2 R21.2 R49.1 R51.1 R52.1 R55.1 R56.1 T1.1 T2.1 TP1.4 U1.8 U1.23 U1.47 U2.2 U3.2 U4.7 U6.8 U6.20 U6.23 U6.35 U6.39 U6.40 U6.44 U6.47 U7.2 Y2.2 Y2.4 | length 2785.1
  Top Layer w6: v2@12366.58,5705 12379.77,5718.2 CN6.B1A12@12379.77,5761.7 ; 12387.58,5104 12387.32,5103.75 U6.20@12341.38,5103.75 12282.32,5103.75 v1(12279.58,5101) 12279.58,5069 12303.89,5044.69 U6.23@12341.38,5044.69 12387.26,5044.69 12406.58,5064 v1(12406.58,5096) ; 12469.58,5347 12479.18,5337.39 U6.8@12479.18,5300.6 ; U6.35@12597.29,4965.95 12597.29,4927.28 12603.58,4921 ; 12613.58,5161 12674.22,5161 U6.44@12676.03,5162.81 12725.38,5162.81 12726.58,5164 ; 12620.58,5065 12621.2,5064.38 U6.39@12676.03,5064.38 12723.95,5064.38 12724.58,5065 ; 12621.58,5207 12636.43,5221.86 U6.47@12676.03,5221.86 12727.43,5221.86 12729.58,5224 ; 12622.58,5084 U6.40@12675.97,5084 ; CN6.A1B12@12633.58,5761.7 12633.58,5729 12644.58,5718 ; U6.40@12676.03,5084.06 12726.63,5084.06 12727.58,5085 ; U1.47@14118.38,4755.9 14118.38,4702.2 14150.58,4670 14234.58,4670 14242.58,4662 14242.58,4638 v2(14240.58,4636) ; v2(14273.58,4584) 14273.58,4544 14242.58,4513 14242.58,4486 14262.58,4466 14280.58,4466 14295.58,4451 U1.23@14295.58,4421.3
  Top Layer w10: v2(13953.58,4533) 13979.67,4559.1 U1.8@14039.67,4559.1 14082.67,4559.1 v1(14094.58,4571) ; C4.1@14089.14,4941 14089.14,4835.44 14118.38,4806.2 U1.47@14118.38,4755.9 ; U1.23@14295.58,4421.3 14295.58,4369 14324.58,4340 v1(14389.58,4340)
  Top Layer w15: C15.1@12301.58,5464.44 C16.1@12371.58,5464.44 12389.01,5464.44 12414.57,5490 U7.2@12451.58,5490
  Bottom Layer w6: 12647.58,5105 12662.58,5120 C8.1@12662.58,5154.44 ; 12949.58,4380 12967.24,4380 R55.1@13008.24,4339 13014.64,4345.4 Q2.2@13071.2,4345.4 ; 12962.58,4234 12964.24,4234 R52.1@13008.24,4190 13024.64,4206.4 Q1.2@13070.2,4206.4 ; R56.1@13008.24,4478 13067.81,4478 Q3.2@13073.2,4483.4 ; v2(14273.58,4584) 14269.58,4588 14271.58,4588 v2@14274.58,4585
  Bottom Layer w10: C13.1@13920.58,4425.44 C28.1@13988.58,4425.44 ; v2(13953.58,4533) 13953.58,4460.44 C28.1@13988.58,4425.44 ; C27.1@14057.58,4426.44 C27.1@14056.58,4425.44 ; v2(14062.58,4379) 14062.58,4419.44 C27.1@14056.58,4425.44 ; C28.1@13988.58,4425.44 C27.1@14056.58,4425.44
  other v1: 12556.13,3196.85 12752.98,3196.85 14721.48,3196.85 14918.33,3196.85 15115.18,3196.85 12162.43,3393.7 12752.98,3393.7 14918.33,3393.7 15312.03,3393.7 14913.58,3587 12162.43,3590.55 12359.28,3590.55 12556.13,3590.55 12752.98,3590.55 15115.18,3590.55 15312.03,3590.55 14556.58,3763 12359.28,3787.4 12752.98,3787.4 12949.83,3787.4 13146.68,3787.4 13737.23,3787.4 15115.18,3787.4 15312.03,3787.4 12359.28,3984.25 15115.18,3984.25 15312.03,3984.25 12359.28,4181.1 14918.33,4181.1 15115.18,4181.1 15312.03,4181.1 15109.58,4364 12752.98,4377.95 13737.23,4377.95 15312.03,4377.95 13561.58,4557 12752.98,4574.8 15115.18,4574.8 15312.03,4574.8 12752.98,4771.65 14918.33,4771.65 15115.18,4771.65 15312.03,4771.65 13939.58,4941 13540.38,4968.5 13737.23,4968.5 15312.03,4968.5 13336.58,5165 14130.93,5165.35 15312.03,5165.35 13233.58,5181 12933.58,5360 13146.68,5362.2 13343.53,5362.2 13540.38,5362.2 15115.18,5362.2 15312.03,5362.2 12162.43,5559.06 13146.68,5559.06 15115.18,5559.06 15312.03,5559.06 13152.58,5741 12162.43,5755.91 12752.98,5755.91 12949.83,5755.91 13343.53,5755.91 13540.38,5755.91 14918.33,5755.91 15115.18,5755.91 15312.03,5755.91 12752.98,5952.76 12949.83,5952.76 13343.53,5952.76 13540.38,5952.76 13737.23,5952.76 13934.08,5952.76 14130.93,5952.76 14327.78,5952.76 14524.63,5952.76 14721.48,5952.76 14918.33,5952.76 15115.18,5952.76
  other v2: 12285.58,3097 12482.43,3097 12679.28,3097 12876.13,3097 13072.98,3097 13269.83,3097 13466.68,3097 13860.38,3097 14057.23,3097 14254.08,3097 14450.93,3097 14647.78,3097 14844.63,3097 15041.48,3097 13670.58,3098 13281.58,3310 13438.58,3310 13296.58,3414 12058.58,3427.8 14879.58,3466 13267.58,3514 12049.58,3625 13926.58,3685 13382.58,3705 13481.58,3707 13595.58,3724 14070.58,3787 12058.58,3821.5 14640.58,3843 13390.58,3849 13594.58,3849 13475.58,3850 13747.58,3852 13923.58,3853 14467.58,3856 14864.58,3863 14032.58,3864 14410.58,3931 14572.58,3931 13456.58,3932 13702.58,3932 13923.58,3932 14057.58,3932 15011.58,3932 13167.58,3999 13920.58,4000 14325.58,4002 12951.58,4005 14836.58,4014 12058.58,4018.35 14555.58,4028 14661.58,4035 12738.58,4088 12425.58,4168 12058.58,4215.2 12722.58,4252 12345.58,4262 14719.58,4274 12444.58,4282 13920.58,4286 12603.58,4309 14025.58,4314 12758.58,4317 12676.58,4318 14076.58,4318 14518.58,4330 14024.58,4354 13923.58,4358 14777.58,4377 13414.58,4384 12061.58,4426 14605.58,4428 14521.58,4430 14662.58,4433 14729.58,4433 12193.58,4444 13579.58,4451 13733.58,4457 13417.58,4475 13874.58,4482 13578.58,4511 13894.58,4535 12232.58,4549 14760.58,4551 13415.58,4560 13898.58,4565 13726.58,4574 13500.58,4581 14233.58,4591 13200.58,4607 12058.58,4608.9 14092.58,4615 13367.58,4616 13652.58,4627 12245.58,4636 13735.58,4643 13505.58,4647 13271.58,4673 13364.58,4683 13475.58,4701 14057.58,4735 14343.58,4743 13376.58,4757 12510.58,4762 12320.58,4764 13868.58,4766 13935.58,4770 13195.58,4772 13497.58,4773 13583.58,4773 14056.58,4776 13274.58,4781 14388.58,4783 14003.58,4784 12074.58,4801 13825.58,4810 13890.58,4815 13777.58,4819 14005.58,4831 12670.58,4851 13856.58,4851 14416.58,4853 14345.58,4861 13560.58,4866 13661.58,4866 13467.58,4867 13752.58,4868 13378.58,4869 12489.58,4881 13999.58,4905 12634.58,4925 12366.58,4926 14003.58,4984 14062.58,4986 12709.58,4990 12651.58,4993 12063.58,5003 13945.58,5016 13653.58,5019 13789.58,5019 13887.58,5019 14004.58,5020 14063.58,5024 13611.58,5084 14014.58,5084 13759.58,5087 13914.58,5087 12413.58,5159 12116.58,5163 12058.58,5199.45 14365.58,5201 12413.58,5226 14031.58,5241 13531.58,5250 14406.58,5257 13626.58,5271 12362.58,5275 12702.58,5277 14360.58,5302 12335.58,5322 12542.58,5354 13626.58,5355 12051.58,5368 12718.58,5368 12788.58,5444 12255.58,5492 12792.58,5544 12055.58,5609 12790.58,5628 12483.58,5637 12166.58,5651 12354.58,5679 12373.58,5704 12713.58,5727 12058.58,5790
  other v3: 13172.58,3923 12957.58,3924 12739.58,3925 13379.58,4002 13636.58,4002 13754.58,4002 13512.58,4003 14051.58,4003 14419.58,4070 13729.58,4073 13202.58,4074 13862.58,4074 14287.58,4074 14048.58,4076 12950.58,4082 12841.58,4087 12615.58,4108 13571.58,4120 13729.58,4120 13273.58,4121 13862.58,4121 13151.58,4122 13382.58,4122 13923.58,4122 14049.58,4123 14621.58,4151 13571.58,4185 13925.58,4185 14048.58,4185 13382.58,4187 13729.58,4187 13193.58,4217 14517.58,4219 14665.58,4219 12609.58,4252 12849.58,4252 13205.58,4267 13126.58,4270 13273.58,4272 13571.58,4279 13729.58,4279 13386.58,4283 13066.58,4308 13274.58,4312 12853.58,4318 13203.58,4318 14345.58,4401 13099.58,4450 13205.58,4451 14345.58,4453 12846.58,4455 13189.58,4506 12675.58,4550 12844.58,4573 13008.58,4594 13094.58,4595 12840.58,4656 12673.58,4658 13003.58,4680 13689.58,4774 13053.58,4778 12925.58,4779 12843.58,4818 13003.58,4868 12836.58,4948 13012.58,5003 12836.58,5060 12608.58,5091 12506.58,5095 12547.58,5145 12922.58,5168 13014.58,5214 12543.79,5245.6 12886.58,5319 12961.58,5319
LD1: LD1.2 U6.10 | length 365.9
  Top Layer w6: LD1.2@12190.75,5465.05 12223.52,5465.05 12281.58,5407 12416.58,5407 12439.81,5383.76 U6.10@12439.81,5300.6
LD2: LD2.2 U6.11 | length 305.6
  Top Layer w6: LD2.2@12191.7,5390.95 12397.62,5390.95 12420.12,5368.45 U6.11@12420.12,5300.6
LD3: LD3.2 U6.12 | length 264.8
  Top Layer w6: LD3.2@12191.75,5314.05 12263.62,5314.05 12301.58,5352 12381.58,5352 12400.44,5333.13 U6.12@12400.44,5300.6
LD4: LD4.2 U6.19 | length 247.6
  Top Layer w6: LD4.2@12191.7,5238.05 12191.7,5151.87 12220.15,5123.43 U6.19@12341.38,5123.43
M-ATLK_RX: RP3.7 U6.31 | length 194.6
  Top Layer w6: U6.31@12518.55,4965.95 12518.55,4920.02 12583.83,4854.75 RP3.7@12583.83,4798.44
M-ATLK_TX: RP3.8 U6.30 | length 189.7
  Top Layer w6: U6.30@12498.86,4965.95 12498.86,4908.71 12552.33,4855.24 RP3.8@12552.33,4798.44
M-NRST: C22.2 P1.4 U6.7 | length 941.8
  Top Layer w10: v1(12498.58,5358) 12498.86,5357.71 U6.7@12498.86,5300.6
  Bottom Layer w6: P1.4@12154.58,4792 12218.58,4856 12218.58,5159 12308.58,5249 12308.58,5358 12355.01,5404.44 C22.2@12496.58,5404.44
  Bottom Layer w10: C22.2@12496.58,5404.44 12498.58,5402.44 v1(12498.58,5358)
M-SWCLK: P1.3 U6.37 | length 586.5
  Top Layer w6: P1.3@12154.58,4892 12155.06,4892 12229.06,4966 v1(12351.58,4966) ; v1(12422.58,5037) 12623.58,5037 12635.57,5025.01 U6.37@12676.03,5025.01
  Bottom Layer w6: v1(12351.58,4966) v1(12422.58,5037)
M-SWDIO: P1.2 U6.34 | length 472.2
  Top Layer w6: P1.2@12154.58,4992 12367.58,4992 12390.58,5015 12561.58,5015 12577.6,4998.97 U6.34@12577.6,4965.95
M-USB_D+: R11.2 U6.33 | length 955.6
  Top Layer w6: U6.33@12557.92,4965.95 12557.92,4925.65 12584.58,4899 12693.6,4899 12702.58,4907.97 v1(12702.58,4928) ; R11.2@12666.24,5597 12699.58,5597 v1(12703.58,5593)
  Bottom Layer w6: v1(12702.58,4928) 12741.58,4967 12741.58,5555 v1(12703.58,5593)
M-USB_D-: R12.2 U6.32 | length 1046.6
  Top Layer w6: U6.32@12538.23,4965.95 12538.23,4928.37 12579.6,4887 12698.58,4887 v1(12724.58,4913) ; R12.2@12666.24,5657 12670.58,5657 v1(12705.58,5622)
  Bottom Layer w6: v1(12705.58,5622) 12753.58,5574 12753.58,4962.03 12724.58,4933.03 v1(12724.58,4913)
M_ATLK_BOOT0: RP2.6 U6.27 | length 170.6
  Top Layer w6: RP2.6@12432.33,4798.44 12432.33,4837.75 12439.81,4845.24 U6.27@12439.81,4965.95
M_ATLK_NRST: RP2.5 U6.28 | length 169.3
  Top Layer w6: U6.28@12459.49,4965.95 12459.49,4919.33 12459.58,4919.24 12459.58,4876 12463.82,4871.76 RP2.5@12463.82,4798.44
M_ATLK_SWCLK: RP2.8 U6.25 | length 187.3
  Top Layer w6: RP2.8@12366.58,4792.66 12366.58,4844.27 12400.44,4878.13 U6.25@12400.44,4965.95
M_ATLK_SWDIO: RP2.7 U6.26 | length 175.5
  Top Layer w6: RP2.7@12400.83,4798.44 12400.83,4843.24 12420.12,4862.54 U6.26@12420.12,4965.95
